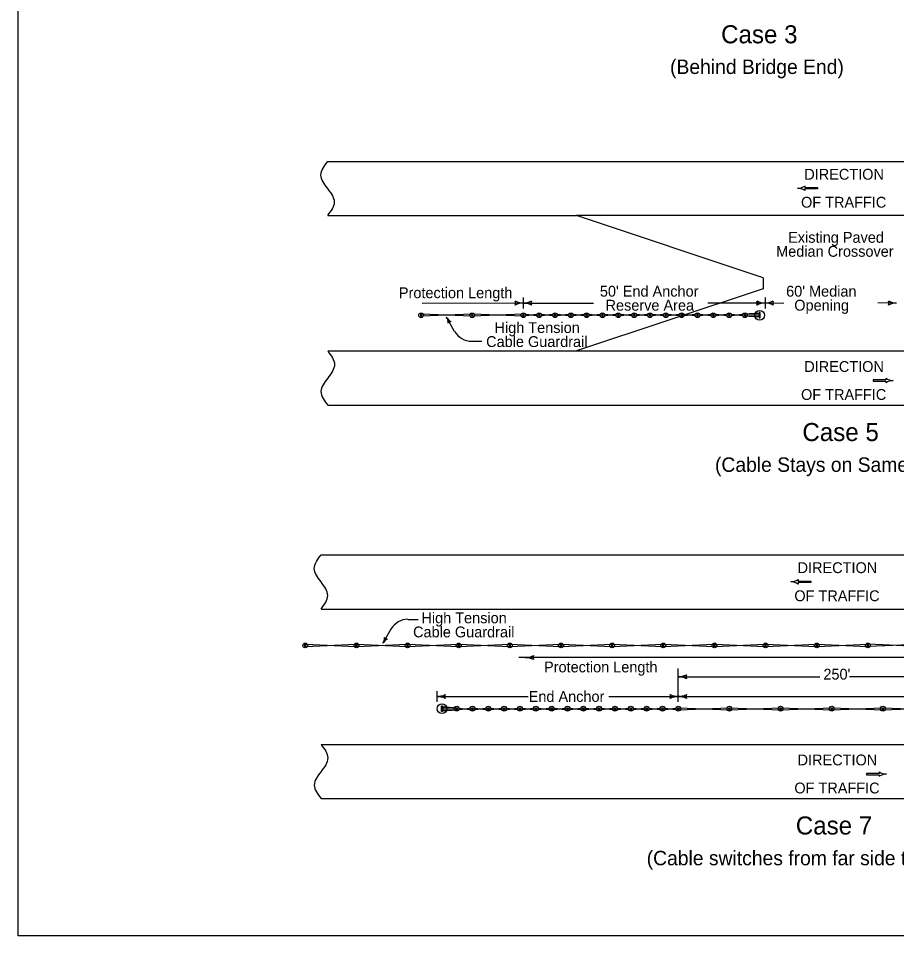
# Model space of a CAD drawing. Extents: x 10133 to 81668, y 7924 to 11018.
# Drawn here: x 10133 to 11106, y 7924 to 8940 of the extents above; entities that cross this region are included whole.
import ezdxf

# ---------------------------------------------------------------- set-up
doc = ezdxf.new("R2010")
doc.units = 0
for name, color, linetype in [('dsnCellElements', 7, 'Continuous'), ('DsnShtRevisedText', 7, 'Continuous'), ('dsnStdDimension', 7, 'Continuous'), ('Level 8', 7, 'Continuous'), ('SheetBorder', 7, 'Continuous')]:
    doc.layers.add(name, color=color, linetype=linetype)

msp = doc.modelspace()

# ---------------------------------------------------------------- linework, layer by layer
at = {"layer": 'dsnCellElements'}
for p, q in [((10635.2, 8612.5), (10579.4, 8610.3)), ((10635.2, 8610.3), (10579.4, 8612.5)), ((10691.9, 8612.5), (10636.1, 8610.3)), ((10691.9, 8610.3), (10636.1, 8612.5)), ((10709.5, 8612.5), (10692.8, 8610.3)), ((10709.5, 8610.3), (10692.8, 8612.5)), ((10727, 8612.5), (10710.4, 8610.3)), ((10727, 8610.3), (10710.4, 8612.5)), ((10744.6, 8612.5), (10727.9, 8610.3)), ((10744.6, 8610.3), (10727.9, 8612.5)), ((10762.1, 8612.5), (10745.5, 8610.3)), ((10762.1, 8610.3), (10745.5, 8612.5)), ((10779.6, 8612.5), (10763, 8610.3)), ((10779.6, 8610.3), (10763, 8612.5)), ((10797.2, 8612.5), (10780.6, 8610.3)), ((10797.2, 8610.3), (10780.6, 8612.5)), ((10814.7, 8612.5), (10798.1, 8610.3)), ((10814.7, 8610.3), (10798.1, 8612.5)), ((10832.3, 8610.3), (10815.7, 8612.5)), ((10832.3, 8612.5), (10815.7, 8610.3)), ((10849.8, 8612.5), (10833.2, 8610.3)), ((10849.8, 8610.3), (10833.2, 8612.5)), ((10867.3, 8612.5), (10850.8, 8610.3)), ((10867.3, 8610.3), (10850.8, 8612.5)), ((10884.9, 8612.5), (10868.3, 8610.3)), ((10884.9, 8610.3), (10868.3, 8612.5)), ((10902.4, 8612.5), (10885.9, 8610.3)), ((10902.4, 8610.3), (10885.9, 8612.5)), ((10920, 8612.5), (10903.4, 8610.3)), ((10920, 8610.3), (10903.4, 8612.5)), ((10937.5, 8612.5), (10921, 8610.3)), ((10937.5, 8610.3), (10921, 8612.5)), ((10954.3, 8613.7), (10937.5, 8612.5)), ((10954.3, 8609.1), (10937.5, 8610.3)), ((10954.3, 8612.5), (10938.5, 8612.5)), ((10954.3, 8610.3), (10938.5, 8610.3)), ((10451, 8246.8), (10506.8, 8244.5)), ((10451, 8244.5), (10506.8, 8246.8)), ((10507.7, 8246.8), (10563.5, 8244.5)), ((10507.7, 8244.5), (10563.5, 8246.8)), ((10564.4, 8246.8), (10620.2, 8244.5)), ((10564.4, 8244.5), (10620.2, 8246.8)), ((10621.1, 8246.8), (10676.9, 8244.5)), ((10621.1, 8244.5), (10676.9, 8246.8)), ((10677.8, 8246.8), (10733.6, 8244.5)), ((10677.8, 8244.5), (10733.6, 8246.8)), ((10734.5, 8246.8), (10790.3, 8244.5)), ((10734.5, 8244.5), (10790.3, 8246.8)), ((10791.2, 8246.8), (10847, 8244.5)), ((10791.2, 8244.5), (10847, 8246.8)), ((10847.9, 8246.8), (10903.7, 8244.5)), ((10847.9, 8244.5), (10903.7, 8246.8)), ((10904.6, 8246.8), (10960.4, 8244.5)), ((10904.6, 8244.5), (10960.4, 8246.8)), ((10961.3, 8246.8), (11017.1, 8244.5)), ((10961.3, 8244.5), (11017.1, 8246.8)), ((11018, 8246.8), (11073.8, 8244.5)), ((11018, 8244.5), (11073.8, 8246.8)), ((11130.5, 8244.5), (11074.7, 8246.8)), ((11130.5, 8246.8), (11074.7, 8244.5)), ((10602.2, 8177.8), (10619, 8176.6)), ((10602.2, 8176.6), (10618, 8176.6)), ((10602.2, 8174.3), (10618, 8174.3)), ((10602.2, 8173.2), (10619, 8174.3)), ((10619, 8176.6), (10635.5, 8174.3)), ((10619, 8174.3), (10635.5, 8176.6)), ((10636.5, 8176.6), (10653.1, 8174.3)), ((10636.5, 8174.3), (10653.1, 8176.6)), ((10654.1, 8176.6), (10670.6, 8174.3)), ((10654.1, 8174.3), (10670.6, 8176.6)), ((10671.6, 8176.6), (10688.2, 8174.3)), ((10671.6, 8174.3), (10688.2, 8176.6)), ((10689.2, 8176.6), (10705.7, 8174.3)), ((10689.2, 8174.3), (10705.7, 8176.6)), ((10706.7, 8176.6), (10723.3, 8174.3)), ((10706.7, 8174.3), (10723.3, 8176.6)), ((10724.2, 8174.3), (10740.8, 8176.6)), ((10724.2, 8176.6), (10740.8, 8174.3)), ((10741.8, 8176.6), (10758.4, 8174.3)), ((10741.8, 8174.3), (10758.4, 8176.6)), ((10759.3, 8176.6), (10775.9, 8174.3)), ((10759.3, 8174.3), (10775.9, 8176.6)), ((10776.9, 8176.6), (10793.5, 8174.3)), ((10776.9, 8174.3), (10793.5, 8176.6)), ((10794.4, 8176.6), (10811, 8174.3)), ((10794.4, 8174.3), (10811, 8176.6)), ((10811.9, 8176.6), (10828.6, 8174.3)), ((10811.9, 8174.3), (10828.6, 8176.6)), ((10829.5, 8176.6), (10846.1, 8174.3)), ((10829.5, 8174.3), (10846.1, 8176.6)), ((10847, 8176.6), (10863.7, 8174.3)), ((10847, 8174.3), (10863.7, 8176.6)), ((10864.6, 8176.6), (10920.4, 8174.3)), ((10864.6, 8174.3), (10920.4, 8176.6)), ((10921.3, 8176.6), (10977.1, 8174.3)), ((10921.3, 8174.3), (10977.1, 8176.6)), ((10978, 8176.6), (11033.8, 8174.3)), ((10978, 8174.3), (11033.8, 8176.6)), ((11034.7, 8176.6), (11090.5, 8174.3)), ((11034.7, 8174.3), (11090.5, 8176.6)), ((11091.4, 8176.6), (11147.2, 8174.3)), ((11091.4, 8174.3), (11147.2, 8176.6))]:
    msp.add_line(p, q, dxfattribs=at)
for points in [[(10579.4, 8610.3), (10579.4, 8612.5), (10578.5, 8612.5), (10578.5, 8610.3)], [(10636.1, 8610.3), (10636.1, 8612.5), (10635.2, 8612.5), (10635.2, 8610.3)], [(10636.1, 8610.3), (10636.1, 8612.5), (10635.2, 8612.5), (10635.2, 8610.3)], [(10692.8, 8610.3), (10692.8, 8612.5), (10691.9, 8612.5), (10691.9, 8610.3)], [(10692.8, 8610.3), (10692.8, 8612.5), (10691.9, 8612.5), (10691.9, 8610.3)], [(10710.4, 8610.3), (10710.4, 8612.5), (10709.5, 8612.5), (10709.5, 8610.3)], [(10727.9, 8610.3), (10727.9, 8612.5), (10727, 8612.5), (10727, 8610.3)], [(10745.5, 8610.3), (10745.5, 8612.5), (10744.6, 8612.5), (10744.6, 8610.3)], [(10763, 8610.3), (10763, 8612.5), (10762.1, 8612.5), (10762.1, 8610.3)], [(10780.6, 8610.3), (10780.6, 8612.5), (10779.6, 8612.5), (10779.6, 8610.3)], [(10798.1, 8610.3), (10798.1, 8612.5), (10797.2, 8612.5), (10797.2, 8610.3)], [(10815.7, 8610.3), (10815.7, 8612.5), (10814.7, 8612.5), (10814.7, 8610.3)], [(10833.2, 8610.3), (10833.2, 8612.5), (10832.3, 8612.5), (10832.3, 8610.3)], [(10850.8, 8610.3), (10850.8, 8612.5), (10849.8, 8612.5), (10849.8, 8610.3)], [(10868.3, 8610.3), (10868.3, 8612.5), (10867.3, 8612.5), (10867.3, 8610.3)], [(10885.9, 8610.3), (10885.9, 8612.5), (10884.9, 8612.5), (10884.9, 8610.3)], [(10903.4, 8610.3), (10903.4, 8612.5), (10902.4, 8612.5), (10902.4, 8610.3)], [(10921, 8610.3), (10921, 8612.5), (10920, 8612.5), (10920, 8610.3)], [(10938.5, 8610.3), (10938.5, 8612.5), (10937.5, 8612.5), (10937.5, 8610.3)], [(10954.9, 8608.4), (10954.9, 8614.4), (10953.7, 8614.4), (10953.7, 8608.4)], [(10450.1, 8244.5), (10450.1, 8246.8), (10451, 8246.8), (10451, 8244.5)], [(10506.8, 8244.5), (10506.8, 8246.8), (10507.7, 8246.8), (10507.7, 8244.5)], [(10506.8, 8244.5), (10506.8, 8246.8), (10507.7, 8246.8), (10507.7, 8244.5)], [(10563.5, 8244.5), (10563.5, 8246.8), (10564.4, 8246.8), (10564.4, 8244.5)], [(10563.5, 8244.5), (10563.5, 8246.8), (10564.4, 8246.8), (10564.4, 8244.5)], [(10620.2, 8244.5), (10620.2, 8246.8), (10621.1, 8246.8), (10621.1, 8244.5)], [(10620.2, 8244.5), (10620.2, 8246.8), (10621.1, 8246.8), (10621.1, 8244.5)], [(10676.9, 8244.5), (10676.9, 8246.8), (10677.8, 8246.8), (10677.8, 8244.5)], [(10676.9, 8244.5), (10676.9, 8246.8), (10677.8, 8246.8), (10677.8, 8244.5)], [(10733.6, 8244.5), (10733.6, 8246.8), (10734.5, 8246.8), (10734.5, 8244.5)], [(10733.6, 8244.5), (10733.6, 8246.8), (10734.5, 8246.8), (10734.5, 8244.5)], [(10790.3, 8244.5), (10790.3, 8246.8), (10791.2, 8246.8), (10791.2, 8244.5)], [(10790.3, 8244.5), (10790.3, 8246.8), (10791.2, 8246.8), (10791.2, 8244.5)], [(10847, 8244.5), (10847, 8246.8), (10847.9, 8246.8), (10847.9, 8244.5)], [(10847, 8244.5), (10847, 8246.8), (10847.9, 8246.8), (10847.9, 8244.5)], [(10903.7, 8244.5), (10903.7, 8246.8), (10904.6, 8246.8), (10904.6, 8244.5)], [(10903.7, 8244.5), (10903.7, 8246.8), (10904.6, 8246.8), (10904.6, 8244.5)], [(10960.4, 8244.5), (10960.4, 8246.8), (10961.3, 8246.8), (10961.3, 8244.5)], [(10960.4, 8244.5), (10960.4, 8246.8), (10961.3, 8246.8), (10961.3, 8244.5)], [(11017.1, 8244.5), (11017.1, 8246.8), (11018, 8246.8), (11018, 8244.5)], [(11017.1, 8244.5), (11017.1, 8246.8), (11018, 8246.8), (11018, 8244.5)], [(11074.7, 8246.8), (11074.7, 8244.5), (11073.8, 8244.5), (11073.8, 8246.8)], [(11073.8, 8244.5), (11073.8, 8246.8), (11074.7, 8246.8), (11074.7, 8244.5)], [(10601.6, 8172.5), (10601.6, 8178.5), (10602.8, 8178.5), (10602.8, 8172.5)], [(10618, 8174.3), (10618, 8176.6), (10619, 8176.6), (10619, 8174.3)], [(10635.5, 8174.3), (10635.5, 8176.6), (10636.5, 8176.6), (10636.5, 8174.3)], [(10653.1, 8174.3), (10653.1, 8176.6), (10654.1, 8176.6), (10654.1, 8174.3)], [(10670.6, 8174.3), (10670.6, 8176.6), (10671.6, 8176.6), (10671.6, 8174.3)], [(10688.2, 8174.3), (10688.2, 8176.6), (10689.2, 8176.6), (10689.2, 8174.3)], [(10705.7, 8174.3), (10705.7, 8176.6), (10706.7, 8176.6), (10706.7, 8174.3)], [(10723.3, 8174.3), (10723.3, 8176.6), (10724.2, 8176.6), (10724.2, 8174.3)], [(10740.8, 8174.3), (10740.8, 8176.6), (10741.8, 8176.6), (10741.8, 8174.3)], [(10758.4, 8174.3), (10758.4, 8176.6), (10759.3, 8176.6), (10759.3, 8174.3)], [(10775.9, 8174.3), (10775.9, 8176.6), (10776.9, 8176.6), (10776.9, 8174.3)], [(10793.5, 8174.3), (10793.5, 8176.6), (10794.4, 8176.6), (10794.4, 8174.3)], [(10811, 8174.3), (10811, 8176.6), (10811.9, 8176.6), (10811.9, 8174.3)], [(10828.6, 8174.3), (10828.6, 8176.6), (10829.5, 8176.6), (10829.5, 8174.3)], [(10846.1, 8174.3), (10846.1, 8176.6), (10847, 8176.6), (10847, 8174.3)], [(10863.7, 8174.3), (10863.7, 8176.6), (10864.6, 8176.6), (10864.6, 8174.3)], [(10863.7, 8174.3), (10863.7, 8176.6), (10864.6, 8176.6), (10864.6, 8174.3)], [(10920.4, 8174.3), (10920.4, 8176.6), (10921.3, 8176.6), (10921.3, 8174.3)], [(10920.4, 8174.3), (10920.4, 8176.6), (10921.3, 8176.6), (10921.3, 8174.3)], [(10977.1, 8174.3), (10977.1, 8176.6), (10978, 8176.6), (10978, 8174.3)], [(10977.1, 8174.3), (10977.1, 8176.6), (10978, 8176.6), (10978, 8174.3)], [(11033.8, 8174.3), (11033.8, 8176.6), (11034.7, 8176.6), (11034.7, 8174.3)], [(11033.8, 8174.3), (11033.8, 8176.6), (11034.7, 8176.6), (11034.7, 8174.3)], [(11090.5, 8174.3), (11090.5, 8176.6), (11091.4, 8176.6), (11091.4, 8174.3)], [(11090.5, 8174.3), (11090.5, 8176.6), (11091.4, 8176.6), (11091.4, 8174.3)]]:
    msp.add_lwpolyline(points, close=True, dxfattribs=at)
for centre, radius in [((10579, 8611.4), 2.66), ((10635.7, 8611.4), 2.66), ((10635.7, 8611.4), 2.66), ((10692.4, 8611.4), 2.66), ((10692.4, 8611.4), 2.66), ((10709.9, 8611.4), 2.66), ((10727.5, 8611.4), 2.66), ((10745, 8611.4), 2.66), ((10762.5, 8611.4), 2.66), ((10780.1, 8611.4), 2.66), ((10797.6, 8611.4), 2.66), ((10815.2, 8611.4), 2.66), ((10832.7, 8611.4), 2.66), ((10850.3, 8611.4), 2.66), ((10867.8, 8611.4), 2.66), ((10885.4, 8611.4), 2.66), ((10902.9, 8611.4), 2.66), ((10920.5, 8611.4), 2.66), ((10938, 8611.4), 2.66), ((10954.3, 8611.4), 5.4), ((10450.6, 8245.6), 2.66), ((10507.3, 8245.6), 2.66), ((10507.3, 8245.6), 2.66), ((10564, 8245.6), 2.66), ((10564, 8245.6), 2.66), ((10620.7, 8245.6), 2.66), ((10620.7, 8245.6), 2.66), ((10677.4, 8245.6), 2.66), ((10677.4, 8245.6), 2.66), ((10734.1, 8245.6), 2.66), ((10734.1, 8245.6), 2.66), ((10790.8, 8245.6), 2.66), ((10790.8, 8245.6), 2.66), ((10847.5, 8245.6), 2.66), ((10847.5, 8245.6), 2.66), ((10904.2, 8245.6), 2.66), ((10904.2, 8245.6), 2.66), ((10960.9, 8245.6), 2.66), ((10960.9, 8245.6), 2.66), ((11017.6, 8245.6), 2.66), ((11017.6, 8245.6), 2.66), ((11074.3, 8245.6), 2.66), ((11074.3, 8245.6), 2.66), ((10602.2, 8175.5), 5.4), ((10618.5, 8175.5), 2.66), ((10636, 8175.5), 2.66), ((10653.6, 8175.5), 2.66), ((10671.1, 8175.5), 2.66), ((10688.7, 8175.5), 2.66), ((10706.2, 8175.5), 2.66), ((10723.8, 8175.5), 2.66), ((10741.3, 8175.5), 2.66), ((10758.9, 8175.5), 2.66), ((10776.4, 8175.5), 2.66), ((10794, 8175.5), 2.66), ((10811.5, 8175.5), 2.66), ((10829, 8175.5), 2.66), ((10846.6, 8175.5), 2.66), ((10864.1, 8175.5), 2.66), ((10864.1, 8175.5), 2.66), ((10920.8, 8175.5), 2.66), ((10920.8, 8175.5), 2.66), ((10977.5, 8175.5), 2.66), ((10977.5, 8175.5), 2.66), ((11034.2, 8175.5), 2.66), ((11034.2, 8175.5), 2.66), ((11090.9, 8175.5), 2.66), ((11090.9, 8175.5), 2.66)]:
    msp.add_circle(centre, radius, dxfattribs=at)
at = {"layer": 'DsnShtRevisedText'}
for p, q in [((10996.2, 8752), (10996.2, 8752)), ((11004.3, 8754.6), (11004.3, 8752.8)), ((11004.3, 8752.8), (11018.3, 8752.8)), ((11018.3, 8751.3), (11004.3, 8751.3)), ((11004.3, 8751.3), (11004.3, 8749.5)), ((11018.3, 8752.8), (11018.3, 8751.3)), ((10692.3, 8630.9), (10692.3, 8618.9)), ((10960.4, 8630.9), (10960.4, 8618.9)), ((10692.3, 8624.9), (10580.3, 8624.5)), ((10692.3, 8624.9), (10770.2, 8624.9)), ((10960.4, 8624.9), (10897, 8624.9)), ((10960.4, 8624.9), (10981.1, 8625.2)), ((11106.2, 8624.9), (11085.4, 8625.2)), ((10616.2, 8593.4), (10607.3, 8609.1)), ((10635, 8582.6), (10646.3, 8582.6)), ((11094.2, 8539.8), (11080.2, 8539.8)), ((11080.2, 8539.8), (11080.2, 8538.2)), ((11080.2, 8538.2), (11094.2, 8538.2)), ((11094.2, 8541.5), (11094.2, 8539.8)), ((11094.2, 8538.2), (11094.2, 8536.5)), ((11102.3, 8539), (11102.3, 8539)), ((10988.8, 8316.1), (10988.8, 8316.1)), ((10996.9, 8318.6), (10996.9, 8316.8)), ((10996.9, 8316.8), (11010.9, 8316.8)), ((11010.9, 8315.3), (10996.9, 8315.3)), ((10996.9, 8315.3), (10996.9, 8313.5)), ((11010.9, 8316.8), (11010.9, 8315.3)), ((10564.4, 8274.4), (10575.6, 8274.4)), ((10545.6, 8263.6), (10536.7, 8248)), ((10723.3, 8232.1), (10687.2, 8232.1)), ((11187.7, 8232.1), (10723.3, 8232.1)), ((10864.1, 8183), (10864.1, 8219.9)), ((10864.1, 8210.9), (11021, 8210.9)), ((11187.7, 8210.9), (11053.8, 8210.9)), ((10596.8, 8183), (10596.8, 8195)), ((10596.8, 8189), (10697.7, 8189)), ((10787.1, 8189), (10864.1, 8189)), ((10864.1, 8189), (11324.5, 8189)), ((11086.8, 8103.8), (11072.8, 8103.8)), ((11072.8, 8103.8), (11072.8, 8102.3)), ((11072.8, 8102.3), (11086.8, 8102.3)), ((11086.8, 8105.6), (11086.8, 8103.8)), ((11086.8, 8102.3), (11086.8, 8100.5)), ((11094.9, 8103.1), (11094.9, 8103.1))]:
    msp.add_line(p, q, dxfattribs=at)
for centre, radius, start, end in [((10995.5, 8768.4), 16.4, 272.352, 302.382), ((10995.5, 8735.7), 16.4, 57.618, 87.648), ((10676.2, 8624.9), 7.39, 342.2666, 17.7333), ((10692.3, 8644.1), 19.1, 241.9275, 270), ((10692.3, 8605.8), 19.1, 90, 118.0725), ((10692.3, 8644.1), 19.1, 270, 298.0725), ((10692.3, 8605.8), 19.1, 61.9275, 90), ((10708.3, 8624.9), 7.39, 162.2666, 197.7334), ((10944.3, 8624.9), 7.39, 342.2667, 17.7334), ((10960.4, 8644.1), 19.1, 241.9275, 270), ((10960.4, 8605.8), 19.1, 90, 118.0725), ((10960.4, 8644.1), 19.1, 270, 298.0725), ((10960.4, 8605.8), 19.1, 61.9275, 90), ((10976.4, 8624.9), 7.39, 162.2666, 197.7334), ((11090.2, 8624.9), 7.39, 342.2667, 17.7334), ((11106.2, 8644.1), 19.1, 241.9275, 270), ((11106.2, 8605.8), 19.1, 90, 118.0725), ((10595.6, 8602.2), 13.6, 2.1589, 30.2314), ((10619.1, 8615.9), 13.6, 210.2314, 238.3038), ((10613.1, 8599.2), 5.25, 102.498, 137.9647), ((10635, 8604.4), 21.8, 210.2243, 270), ((11102.9, 8555.4), 16.4, 237.618, 267.648), ((11102.9, 8522.6), 16.4, 92.352, 122.382), ((10988.2, 8332.4), 16.4, 272.352, 302.382), ((10988.2, 8299.7), 16.4, 57.618, 87.648), ((10564.4, 8252.7), 21.8, 90, 149.7757), ((10525, 8254.8), 13.6, 329.7686, 357.8411), ((10548.5, 8241.1), 13.6, 121.6962, 149.7686), ((10542.4, 8257.8), 5.25, 222.0353, 257.502), ((10694.5, 8251.2), 19.1, 270, 298.0725), ((10710.5, 8232.1), 7.39, 162.2666, 197.7334), ((10694.5, 8213), 19.1, 61.9275, 90), ((10864.1, 8230), 19.1, 270, 298.0725), ((10880.2, 8210.9), 7.39, 162.2666, 197.7334), ((10864.1, 8191.8), 19.1, 61.9275, 90), ((10596.8, 8208.1), 19.1, 270, 298.0725), ((10596.8, 8169.9), 19.1, 61.9275, 90), ((10612.8, 8189), 7.39, 162.2666, 197.7334), ((10848.1, 8189), 7.39, 342.2666, 17.7333), ((10864.1, 8208.1), 19.1, 241.9275, 270), ((10864.1, 8169.9), 19.1, 90, 118.0725), ((10864.1, 8208.1), 19.1, 270, 298.0725), ((10864.1, 8169.9), 19.1, 61.9275, 90), ((10880.2, 8189), 7.39, 162.2666, 197.7334), ((11095.5, 8119.4), 16.4, 237.618, 267.648), ((11095.5, 8086.7), 16.4, 92.352, 122.382)]:
    msp.add_arc(centre, radius, start, end, dxfattribs=at)
at = {"layer": 'dsnStdDimension'}
for p, q in [((10475.5, 8781.8), (11591.1, 8781.8)), ((10475.5, 8721.8), (10751.3, 8721.8)), ((10958.3, 8652.8), (10751.3, 8721.8)), ((11315.3, 8721.8), (10751.3, 8721.8)), ((10958.3, 8652.8), (10958.3, 8640.8)), ((10958.3, 8640.8), (10751.3, 8571.8)), ((10475.5, 8571.8), (10754.4, 8571.8)), ((10754.4, 8571.8), (11315.3, 8571.8)), ((10475.5, 8511.8), (11591.1, 8511.8)), ((10468.1, 8345.9), (11953.1, 8345.9)), ((10468.1, 8285.9), (11361.5, 8285.9)), ((10468.1, 8135.9), (11361.5, 8135.9)), ((10468.1, 8075.9), (11953.1, 8075.9))]:
    msp.add_line(p, q, dxfattribs=at)
for points in [[(10475.5, 8721.8), (10483, 8736.8), (10475.5, 8751.8), (10468, 8766.8), (10475.5, 8781.8)], [(10475.5, 8571.8), (10483, 8556.8), (10475.5, 8541.8), (10468, 8526.8), (10475.5, 8511.8)], [(10468.1, 8285.9), (10475.6, 8300.9), (10468.1, 8315.9), (10460.6, 8330.9), (10468.1, 8345.9)], [(10468.1, 8135.9), (10475.6, 8120.9), (10468.1, 8105.9), (10460.6, 8090.9), (10468.1, 8075.9)]]:
    msp.add_spline(points, degree=3, dxfattribs=at)
at = {"layer": 'SheetBorder'}
msp.add_lwpolyline([(10132.5, 9944), (13267.5, 9944), (13267.5, 7924), (10132.5, 7924)], close=True, dxfattribs=at)

# ---------------------------------------------------------------- texts
at = {"layer": 'DsnShtRevisedText'}
for s, p in [('DIRECTION', (11003.8, 8761.6)), ('OF TRAFFIC', (11000.2, 8730.6)), ('Existing Paved', (10985.9, 8691.7)), ('Median Crossover', (10972.6, 8676.2)), ('Protection Length', (10554.4, 8630.3)), ("50' End Anchor", (10777.2, 8632)), ("60' Median", (10983.7, 8632)), ('Opening', (10992.7, 8616.5)), ('Reserve Area', (10783.5, 8616.5)), ('High Tension', (10660.4, 8591.7)), ('Cable Guardrail', (10651.1, 8576.2)), ('DIRECTION', (11003.8, 8548.6)), ('OF TRAFFIC', (11000.2, 8517.6)), ('DIRECTION', (10996.4, 8325.7)), ('OF TRAFFIC', (10992.8, 8294.6)), ('High Tension', (10579.4, 8270.1)), ('Cable Guardrail', (10570.1, 8254.5)), ('Protection Length', (10715.3, 8215.7)), ("250'", (11025, 8207.7)), ('End Anchor', (10698.3, 8183)), ('DIRECTION', (10996.4, 8112.7)), ('OF TRAFFIC', (10992.8, 8081.6))]:
    msp.add_text(s, height=12, dxfattribs=at).set_placement(p)
at = {"layer": 'Level 8'}
for s, height, p in [('Case 3', 20, (10911.6, 8912.7)), ('(Behind Bridge End)', 16, (10855, 8878.7)), ('Case 5', 20, (11001.7, 8472)), ('(Cable Stays on Same Side)', 16, (10904.8, 8437.9)), ('Case 7', 20, (10994.4, 8036.1)), ('(Cable switches from far side to near side)', 16, (10829.1, 8002))]:
    msp.add_text(s, height=height, dxfattribs=at).set_placement(p)

doc.saveas('drawing.dxf')
